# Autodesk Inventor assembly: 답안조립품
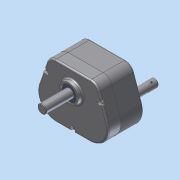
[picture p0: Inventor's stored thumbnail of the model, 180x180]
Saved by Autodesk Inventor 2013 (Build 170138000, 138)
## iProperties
Created: 2014-12
Part Number: 답안조립품
Document SubType Name: Assembly
Designer: dgall
Author: dgall
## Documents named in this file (13)
- C:\Documents and Settings\dgall\바탕 화면\441208V1044\답안조립품.iam
- C:\Documents and Settings\dgall\바탕 화면\441208V1044\본체.ipt
- C:\Documents and Settings\dgall\바탕 화면\441208V1044\베어링- 6203.ipt
- C:\Documents and Settings\dgall\바탕 화면\441208V1044\베어링- 6202.ipt
- C:\Documents and Settings\dgall\바탕 화면\441208V1044\메인축.ipt
- C:\Documents and Settings\dgall\바탕 화면\441208V1044\서브축.ipt
- C:\Documents and Settings\dgall\바탕 화면\441208V1044\키5x5.ipt
- C:\Documents and Settings\dgall\바탕 화면\441208V1044\메인기어.ipt
- C:\Documents and Settings\dgall\바탕 화면\441208V1044\서브기어.ipt
- C:\Documents and Settings\dgall\바탕 화면\441208V1044\멈춤링.ipt
- C:\Documents and Settings\dgall\바탕 화면\441208V1044\커버.ipt
- C:\Documents and Settings\dgall\바탕 화면\441208V1044\오일시일-D-17.ipt
- C:\Documents and Settings\dgall\바탕 화면\441208V1044\오일시일-D-15.ipt
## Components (11 placed, 5 different names)
1. KS B 2023 6203 - 17 x 40 x 12:1
2. KS B 2023 6202 - 15 x 35 x 11:1
3. KS B 2023 6202 - 15 x 35 x 11:2
4. KS B 1336 17 x 1:2
5. KS B 1336 17 x 1:3
6. KS B 2023 6203 - 17 x 40 x 12:2
7. KS B 2023 6203 - 17 x 40 x 12:3
8. KS B 2023 6203 - 17 x 40 x 12:4
9. KS B 2804 D D - 17 30 8:1
10. KS B 2804 D D - 15 30 7:1
11. KS B 2804 D D - 15 30 7:2
